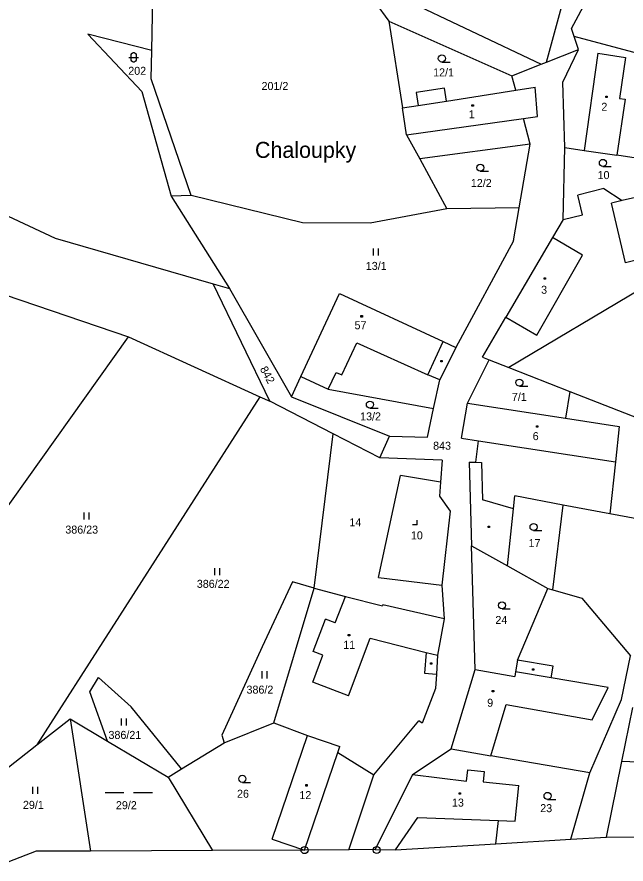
# Model space of a CAD drawing. Extents: x -791032 to -787751, y -1106872 to -1104403.
# Drawn here: x -789231 to -789101.8, y -1105221.6 to -1105041.7 of the extents above; entities that cross this region are included whole.
import ezdxf

# ---------------------------------------------------------------- set-up
doc = ezdxf.new("R2010")
doc.units = 0
for name, color, linetype in [('Vrstva 1', 7, 'Continuous'), ('Vrstva 14', 7, 'Continuous'), ('Vrstva 15', 7, 'Continuous'), ('Vrstva 2', 7, 'Continuous'), ('Vrstva 23', 7, 'Continuous'), ('Vrstva 25', 7, 'Continuous'), ('Vrstva 28', 7, 'Continuous'), ('Vrstva 36', 7, 'Continuous')]:
    doc.layers.add(name, color=color, linetype=linetype)

msp = doc.modelspace()

# ---------------------------------------------------------------- linework, layer by layer
at = {"layer": 'Vrstva 1'}
for p, q in [((-789178.54, -1105023.79), (-789119.8, -1105051.77)), ((-789113.36, -1105044.2), (-789102.89, -1105024.45)), ((-789202.43, -1105048.85), (-789202.19, -1105036.83)), ((-789155.02, -1105038.66), (-789152.12, -1105042.62)), ((-789118.67, -1105051.32), (-789115.06, -1105038.01)), ((-789152.12, -1105042.62), (-789126.03, -1105054.24)), ((-789152.12, -1105042.62), (-789149.25, -1105061.04)), ((-789112.82, -1105045.85), (-789113.36, -1105044.2)), ((-789202.43, -1105048.85), (-789215.98, -1105045.42)), ((-789215.98, -1105045.42), (-789204.53, -1105057.57)), ((-789098.24, -1105049.77), (-789112.82, -1105045.85)), ((-789111.91, -1105048.65), (-789112.82, -1105045.85)), ((-789202.55, -1105054.9), (-789202.43, -1105048.85)), ((-789118.67, -1105051.32), (-789111.91, -1105048.65)), ((-789115.2, -1105055.58), (-789111.91, -1105048.65)), ((-789119.8, -1105051.77), (-789118.67, -1105051.32)), ((-789126.03, -1105054.24), (-789119.8, -1105051.77)), ((-789194.11, -1105079.65), (-789202.55, -1105054.9)), ((-789125.2, -1105057.3), (-789126.03, -1105054.24)), ((-789140.29, -1105056.86), (-789146.31, -1105057.8)), ((-789139.86, -1105059.58), (-789140.29, -1105056.86)), ((-789125.2, -1105057.3), (-789121.04, -1105056.65)), ((-789120.61, -1105062.86), (-789121.04, -1105056.65)), ((-789114.79, -1105069.45), (-789115.2, -1105055.58)), ((-789204.53, -1105057.57), (-789198.35, -1105079.82)), ((-789146.31, -1105057.8), (-789145.89, -1105060.52)), ((-789139.86, -1105059.58), (-789125.2, -1105057.3)), ((-789149.25, -1105061.04), (-789145.89, -1105060.52)), ((-789148.36, -1105066.77), (-789149.25, -1105061.04)), ((-789278.51, -1105062.82), (-789222.93, -1105088.68)), ((-789123.58, -1105063.28), (-789120.61, -1105062.86)), ((-789122.11, -1105068.74), (-789123.58, -1105063.28)), ((-789148.36, -1105066.77), (-789145.58, -1105071.89)), ((-789122.11, -1105068.74), (-789145.58, -1105071.89)), ((-789124.47, -1105082.24), (-789122.11, -1105068.74)), ((-789115.1, -1105084.74), (-789114.79, -1105069.45)), ((-789114.79, -1105069.45), (-789110.65, -1105070.06)), ((-789110.65, -1105070.06), (-789103.77, -1105071.08)), ((-789098.72, -1105071.83), (-789103.77, -1105071.08)), ((-789145.58, -1105071.89), (-789139.84, -1105082.48)), ((-789106.48, -1105078.19), (-789112.04, -1105079.57)), ((-789106.48, -1105078.19), (-789102.58, -1105080.73)), ((-789194.11, -1105079.65), (-789198.35, -1105079.82)), ((-789198.35, -1105079.82), (-789185.94, -1105099.42)), ((-789170.48, -1105085.44), (-789194.11, -1105079.65)), ((-789111.01, -1105083.72), (-789112.04, -1105079.57)), ((-789098.52, -1105079.77), (-789102.58, -1105080.73)), ((-789139.84, -1105082.48), (-789156.07, -1105085.5)), ((-789124.47, -1105082.24), (-789139.84, -1105082.48)), ((-789125.7, -1105089.28), (-789124.47, -1105082.24)), ((-789115.1, -1105084.74), (-789111.01, -1105083.72)), ((-789156.07, -1105085.5), (-789170.48, -1105085.44)), ((-789115.1, -1105084.74), (-789117.37, -1105088.6)), ((-789222.93, -1105088.68), (-789189.39, -1105098.42)), ((-789117.37, -1105088.6), (-789127.27, -1105105.47)), ((-789125.7, -1105089.28), (-789137.94, -1105111.94)), ((-789177.4, -1105123.32), (-789189.39, -1105098.42)), ((-789189.39, -1105098.42), (-789185.94, -1105099.42)), ((-789185.94, -1105099.42), (-789172.78, -1105122.42)), ((-789098.56, -1105099.48), (-789126.63, -1105116.18)), ((-789233.54, -1105100.77), (-789207.36, -1105109.66)), ((-789170.78, -1105118.09), (-789162.62, -1105100.45)), ((-789162.62, -1105100.45), (-789140.61, -1105110.62)), ((-789132.26, -1105113.97), (-789127.27, -1105105.47)), ((-789249, -1105168.08), (-789207.36, -1105109.66)), ((-789207.36, -1105109.66), (-789179.49, -1105122.37)), ((-789140.61, -1105110.62), (-789137.94, -1105111.94)), ((-789137.94, -1105111.94), (-789141.33, -1105118.77)), ((-789132.26, -1105113.97), (-789130.85, -1105114.52)), ((-789135.42, -1105123.71), (-789130.85, -1105114.52)), ((-789130.85, -1105114.52), (-789126.63, -1105116.18)), ((-789126.63, -1105116.18), (-789113.73, -1105121.26)), ((-789172.78, -1105122.42), (-789170.78, -1105118.09)), ((-789170.78, -1105118.09), (-789164.97, -1105120.78)), ((-789142.62, -1105124.88), (-789141.33, -1105118.77)), ((-789164.97, -1105120.78), (-789142.62, -1105124.88)), ((-789113.73, -1105121.26), (-789114.64, -1105126.96)), ((-789113.73, -1105121.26), (-789084.71, -1105132.68)), ((-789179.49, -1105122.37), (-789226.84, -1105196.33)), ((-789179.49, -1105122.37), (-789177.4, -1105123.32)), ((-789163.93, -1105130.24), (-789177.4, -1105123.32)), ((-789172.78, -1105122.42), (-789152.02, -1105130.76)), ((-789143.9, -1105130.94), (-789142.62, -1105124.88)), ((-789136.72, -1105131.17), (-789135.42, -1105123.71)), ((-789135.42, -1105123.71), (-789114.64, -1105126.96)), ((-789114.64, -1105126.96), (-789103.28, -1105128.73)), ((-789103.28, -1105128.73), (-789104.06, -1105136.21)), ((-789167.98, -1105163.02), (-789163.93, -1105130.24)), ((-789154.05, -1105135.32), (-789163.93, -1105130.24)), ((-789154.05, -1105135.32), (-789152.02, -1105130.76)), ((-789152.02, -1105130.76), (-789143.9, -1105130.94)), ((-789136.72, -1105131.17), (-789133.11, -1105131.73)), ((-789133.7, -1105136.3), (-789133.11, -1105131.73)), ((-789140.82, -1105135.86), (-789154.05, -1105135.32)), ((-789140.82, -1105135.86), (-789141.17, -1105140.52)), ((-789135.08, -1105136.24), (-789133.7, -1105136.3)), ((-789135.08, -1105136.24), (-789134.56, -1105154.02)), ((-789104.06, -1105136.21), (-789105.22, -1105147.22)), ((-789154.31, -1105160.75), (-789149.66, -1105139.08)), ((-789141.17, -1105140.52), (-789149.66, -1105139.08)), ((-789141.17, -1105140.52), (-789141.4, -1105143.51)), ((-789141.4, -1105143.51), (-789139.12, -1105146.69)), ((-789125.68, -1105146.2), (-789125.39, -1105143.45)), ((-789115.14, -1105145.37), (-789125.39, -1105143.45)), ((-789139.12, -1105146.69), (-789140.86, -1105162.4)), ((-789126.93, -1105158.29), (-789125.68, -1105146.2)), ((-789117.31, -1105163.38), (-789115.14, -1105145.37)), ((-789105.22, -1105147.22), (-789115.14, -1105145.37)), ((-789086.15, -1105150.78), (-789105.22, -1105147.22)), ((-789134.56, -1105154.02), (-789126.93, -1105158.29)), ((-789133.79, -1105180.33), (-789134.56, -1105154.02)), ((-789126.93, -1105158.29), (-789118.36, -1105163.08)), ((-789154.31, -1105160.75), (-789140.86, -1105162.4)), ((-789172.59, -1105161.65), (-789179.02, -1105175.48)), ((-789176.5, -1105191.61), (-789167.98, -1105163.02)), ((-789167.98, -1105163.02), (-789172.59, -1105161.65)), ((-789167.98, -1105163.02), (-789161.34, -1105164.77)), ((-789140.86, -1105162.4), (-789140.4, -1105169.52)), ((-789161.34, -1105164.77), (-789153.5, -1105166.81)), ((-789124.81, -1105178.29), (-789118.36, -1105163.08)), ((-789118.36, -1105163.08), (-789117.31, -1105163.38)), ((-789117.31, -1105163.38), (-789111.16, -1105165.15)), ((-789153.41, -1105166.57), (-789153.5, -1105166.81)), ((-789140.4, -1105169.52), (-789153.41, -1105166.57)), ((-789111.16, -1105165.15), (-789100.83, -1105177.38)), ((-789140.4, -1105169.52), (-789141.8, -1105177.29)), ((-789179.02, -1105175.48), (-789187.58, -1105194.23)), ((-789141.8, -1105177.29), (-789142.03, -1105181.32)), ((-789102.76, -1105186.64), (-789100.83, -1105177.38)), ((-789124.81, -1105178.29), (-789125.24, -1105180.78)), ((-789138.91, -1105197.17), (-789133.79, -1105180.33)), ((-789133.79, -1105180.33), (-789125.41, -1105181.77)), ((-789125.24, -1105180.78), (-789125.41, -1105181.77)), ((-789215.56, -1105185.06), (-789213.74, -1105182.03)), ((-789213.74, -1105182.03), (-789206.78, -1105188.22)), ((-789142.03, -1105181.32), (-789142.21, -1105184.34)), ((-789142.21, -1105184.34), (-789145.07, -1105191.66)), ((-789211.8, -1105195.49), (-789215.56, -1105185.06)), ((-789109.47, -1105202.22), (-789102.76, -1105186.64)), ((-789196.13, -1105201.4), (-789206.78, -1105188.22)), ((-789102.69, -1105199.82), (-789100.37, -1105188.37)), ((-789226.84, -1105196.33), (-789219.72, -1105190.75)), ((-789219.72, -1105190.75), (-789215.47, -1105218.84)), ((-789219.72, -1105190.75), (-789211.8, -1105195.49)), ((-789187.04, -1105195.84), (-789176.5, -1105191.61)), ((-789176.5, -1105191.61), (-789169.41, -1105194.33)), ((-789155.31, -1105202.64), (-789145.74, -1105191.21)), ((-789145.07, -1105191.66), (-789145.74, -1105191.21)), ((-789187.58, -1105194.23), (-789187.04, -1105195.84)), ((-789176.91, -1105216.33), (-789169.41, -1105194.33)), ((-789169.41, -1105194.33), (-789162.53, -1105196.67)), ((-789235.62, -1105203.21), (-789226.84, -1105196.33)), ((-789211.8, -1105195.49), (-789198.99, -1105203.15)), ((-789196.13, -1105201.4), (-789187.04, -1105195.84)), ((-789162.95, -1105197.91), (-789162.53, -1105196.67)), ((-789147.12, -1105202.62), (-789138.91, -1105197.17)), ((-789138.91, -1105197.17), (-789130.48, -1105198.62)), ((-789162.95, -1105197.91), (-789155.31, -1105202.64)), ((-789109.47, -1105202.22), (-789130.48, -1105198.62)), ((-789105.94, -1105215.9), (-789102.69, -1105199.82)), ((-789096.99, -1105200.08), (-789102.69, -1105199.82)), ((-789198.99, -1105203.15), (-789196.13, -1105201.4)), ((-789135.62, -1105204), (-789135.39, -1105201.62)), ((-789135.39, -1105201.62), (-789131.9, -1105201.96)), ((-789131.9, -1105201.96), (-789132.12, -1105204.15)), ((-789113.53, -1105216.35), (-789109.47, -1105202.22)), ((-789198.99, -1105203.15), (-789189.58, -1105218.74)), ((-789160.6, -1105218.59), (-789155.31, -1105202.64)), ((-789147.12, -1105202.62), (-789155.06, -1105218.55)), ((-789147.12, -1105202.62), (-789135.62, -1105204)), ((-789132.12, -1105204.15), (-789124.56, -1105204.91)), ((-789125.32, -1105212.51), (-789124.56, -1105204.91)), ((-789129.42, -1105217.3), (-789128.85, -1105212.38)), ((-789128.85, -1105212.38), (-789125.32, -1105212.51)), ((-789176.91, -1105216.33), (-789170.03, -1105218.67)), ((-789129.42, -1105217.3), (-789113.53, -1105216.35)), ((-789113.53, -1105216.35), (-789105.94, -1105215.9)), ((-789105.94, -1105215.9), (-789070.94, -1105215.53)), ((-789189.58, -1105218.74), (-789215.47, -1105218.84)), ((-789170.03, -1105218.67), (-789189.58, -1105218.74)), ((-789160.6, -1105218.59), (-789170.03, -1105218.67)), ((-789155.06, -1105218.55), (-789160.6, -1105218.59)), ((-789155.06, -1105218.55), (-789150.68, -1105218.58)), ((-789150.68, -1105218.58), (-789129.42, -1105217.3)), ((-789226.96, -1105218.88), (-789243.84, -1105225.4)), ((-789215.47, -1105218.84), (-789226.96, -1105218.88))]:
    msp.add_line(p, q, dxfattribs=at)
at = {"layer": 'Vrstva 2'}
for p, q in [((-789107.8, -1105049.45), (-789110.65, -1105070.06)), ((-789107.8, -1105049.45), (-789101.91, -1105050.33)), ((-789101.91, -1105050.33), (-789103.2, -1105059.03)), ((-789145.89, -1105060.52), (-789139.86, -1105059.58)), ((-789102.01, -1105059.21), (-789103.77, -1105071.08)), ((-789103.2, -1105059.03), (-789102.01, -1105059.21)), ((-789148.36, -1105066.77), (-789123.58, -1105063.28)), ((-789102.58, -1105080.73), (-789104.9, -1105081.28)), ((-789101.92, -1105093.92), (-789104.9, -1105081.28)), ((-789111.01, -1105092.29), (-789117.37, -1105088.6)), ((-789120.75, -1105109.27), (-789111.01, -1105092.29)), ((-789095.52, -1105092.41), (-789101.92, -1105093.92)), ((-789127.27, -1105105.47), (-789120.75, -1105109.27)), ((-789143.82, -1105117.74), (-789140.61, -1105110.62)), ((-789162.13, -1105117.75), (-789158.95, -1105110.92)), ((-789158.95, -1105110.92), (-789143.82, -1105117.74)), ((-789164.97, -1105120.78), (-789163.31, -1105117.2)), ((-789163.31, -1105117.2), (-789162.13, -1105117.75)), ((-789141.33, -1105118.77), (-789143.82, -1105117.74)), ((-789133.11, -1105131.73), (-789104.06, -1105136.21)), ((-789133.7, -1105136.3), (-789132.48, -1105136.35)), ((-789132.48, -1105136.35), (-789132.25, -1105144.25)), ((-789125.68, -1105146.2), (-789132.25, -1105144.25)), ((-789163.49, -1105170.42), (-789161.34, -1105164.77)), ((-789168.19, -1105176.5), (-789165.58, -1105169.63)), ((-789163.49, -1105170.42), (-789165.58, -1105169.63)), ((-789160.71, -1105185.86), (-789156.09, -1105173.66)), ((-789156.09, -1105173.66), (-789144.22, -1105176.67)), ((-789168.28, -1105182.98), (-789166.11, -1105177.29)), ((-789166.11, -1105177.29), (-789168.19, -1105176.5)), ((-789144.22, -1105176.67), (-789144.57, -1105181.06)), ((-789144.22, -1105176.67), (-789141.8, -1105177.29)), ((-789117.26, -1105179.58), (-789124.81, -1105178.29)), ((-789117.69, -1105182.08), (-789125.24, -1105180.78)), ((-789117.69, -1105182.08), (-789117.26, -1105179.58)), ((-789144.57, -1105181.06), (-789142.03, -1105181.32)), ((-789105.6, -1105184.15), (-789117.69, -1105182.08)), ((-789160.71, -1105185.86), (-789168.28, -1105182.98)), ((-789109, -1105191), (-789105.6, -1105184.15)), ((-789130.48, -1105198.62), (-789127.21, -1105187.75)), ((-789127.21, -1105187.75), (-789109, -1105191)), ((-789170.03, -1105218.67), (-789162.95, -1105197.91)), ((-789150.68, -1105218.58), (-789146, -1105211.75)), ((-789146, -1105211.75), (-789128.85, -1105212.38))]:
    msp.add_line(p, q, dxfattribs=at)
at = {"layer": 'Vrstva 23'}
for p, q in [((-789206.78, -1105049.71), (-789206.68, -1105049.51)), ((-789206.68, -1105049.51), (-789206.58, -1105049.41)), ((-789206.58, -1105049.41), (-789206.38, -1105049.31)), ((-789206.38, -1105049.31), (-789206.18, -1105049.31)), ((-789206.18, -1105049.31), (-789205.98, -1105049.41)), ((-789205.98, -1105049.41), (-789205.88, -1105049.51)), ((-789205.88, -1105049.51), (-789205.78, -1105049.71)), ((-789207.28, -1105050.31), (-789205.28, -1105050.31)), ((-789206.78, -1105050.91), (-789206.78, -1105049.71)), ((-789206.68, -1105051.11), (-789206.78, -1105050.91)), ((-789206.58, -1105051.21), (-789206.68, -1105051.11)), ((-789206.38, -1105051.31), (-789206.58, -1105051.21)), ((-789206.18, -1105051.31), (-789206.38, -1105051.31)), ((-789205.98, -1105051.21), (-789206.18, -1105051.31)), ((-789205.88, -1105051.11), (-789205.98, -1105051.21)), ((-789205.78, -1105050.91), (-789205.88, -1105051.11)), ((-789205.78, -1105049.71), (-789205.78, -1105050.91)), ((-789140.88, -1105051.3), (-789139.13, -1105051.3)), ((-789132.72, -1105074.49), (-789130.97, -1105074.49)), ((-789106.7, -1105073.47), (-789104.95, -1105073.47)), ((-789155.39, -1105092.41), (-789155.39, -1105090.91)), ((-789154.39, -1105090.91), (-789154.39, -1105092.41)), ((-789124.41, -1105120.13), (-789122.66, -1105120.13)), ((-789156.15, -1105124.8), (-789154.4, -1105124.8)), ((-789216.79, -1105148.46), (-789216.79, -1105146.96)), ((-789215.79, -1105146.96), (-789215.79, -1105148.46)), ((-789146.13, -1105149.58), (-789146.13, -1105148.58)), ((-789146.13, -1105149.58), (-789147.13, -1105149.58)), ((-789121.41, -1105150.79), (-789119.66, -1105150.79)), ((-789189.05, -1105160.26), (-789189.05, -1105158.76)), ((-789188.05, -1105158.76), (-789188.05, -1105160.26)), ((-789128.11, -1105167.43), (-789126.36, -1105167.43)), ((-789179.01, -1105182.18), (-789179.01, -1105180.68)), ((-789178.01, -1105180.68), (-789178.01, -1105182.18)), ((-789208.86, -1105192.22), (-789208.86, -1105190.72)), ((-789207.86, -1105190.72), (-789207.86, -1105192.22)), ((-789183.21, -1105204.26), (-789181.46, -1105204.26)), ((-789227.67, -1105206.69), (-789227.67, -1105205.19)), ((-789226.67, -1105205.19), (-789226.67, -1105206.69)), ((-789212.355, -1105206.42), (-789208.335, -1105206.42)), ((-789206.325, -1105206.42), (-789202.305, -1105206.42)), ((-789118.44, -1105207.89), (-789116.69, -1105207.89))]:
    msp.add_line(p, q, dxfattribs=at)
for centre in [(-789140.88, -1105050.55), (-789132.72, -1105073.74), (-789106.7, -1105072.72), (-789124.41, -1105119.38), (-789156.15, -1105124.05), (-789121.41, -1105150.04), (-789128.11, -1105166.68), (-789183.21, -1105203.51), (-789118.44, -1105207.14)]:
    msp.add_circle(centre, 0.75, dxfattribs=at)
at = {"layer": 'Vrstva 25'}
for p, q in [((-789106.11, -1105058.57), (-789105.81, -1105058.57)), ((-789106.11, -1105058.87), (-789106.11, -1105058.57)), ((-789105.81, -1105058.57), (-789105.81, -1105058.87)), ((-789134.48, -1105060.36), (-789134.18, -1105060.36)), ((-789134.48, -1105060.66), (-789134.48, -1105060.36)), ((-789134.18, -1105060.36), (-789134.18, -1105060.66)), ((-789105.81, -1105058.87), (-789106.11, -1105058.87)), ((-789134.18, -1105060.66), (-789134.48, -1105060.66)), ((-789119.16, -1105097.13), (-789118.86, -1105097.13)), ((-789119.16, -1105097.43), (-789119.16, -1105097.13)), ((-789118.86, -1105097.43), (-789119.16, -1105097.43)), ((-789118.86, -1105097.13), (-789118.86, -1105097.43)), ((-789158.05, -1105105.15), (-789157.75, -1105105.15)), ((-789158.05, -1105105.45), (-789158.05, -1105105.15)), ((-789157.75, -1105105.45), (-789158.05, -1105105.45)), ((-789157.75, -1105105.15), (-789157.75, -1105105.45)), ((-789141.1, -1105114.66), (-789140.8, -1105114.66)), ((-789141.1, -1105114.96), (-789141.1, -1105114.66)), ((-789140.8, -1105114.96), (-789141.1, -1105114.96)), ((-789140.8, -1105114.66), (-789140.8, -1105114.96)), ((-789120.82, -1105128.53), (-789120.52, -1105128.53)), ((-789120.82, -1105128.83), (-789120.82, -1105128.53)), ((-789120.52, -1105128.83), (-789120.82, -1105128.83)), ((-789120.52, -1105128.53), (-789120.52, -1105128.83)), ((-789131.04, -1105149.88), (-789130.74, -1105149.88)), ((-789131.04, -1105150.18), (-789131.04, -1105149.88)), ((-789130.74, -1105150.18), (-789131.04, -1105150.18)), ((-789130.74, -1105149.88), (-789130.74, -1105150.18)), ((-789160.73, -1105172.88), (-789160.43, -1105172.88)), ((-789160.73, -1105173.18), (-789160.73, -1105172.88)), ((-789160.43, -1105173.18), (-789160.73, -1105173.18)), ((-789160.43, -1105172.88), (-789160.43, -1105173.18)), ((-789143.31, -1105178.9), (-789143.01, -1105178.9)), ((-789143.31, -1105179.2), (-789143.31, -1105178.9)), ((-789143.01, -1105179.2), (-789143.31, -1105179.2)), ((-789143.01, -1105178.9), (-789143.01, -1105179.2)), ((-789121.64, -1105180.17), (-789121.34, -1105180.17)), ((-789121.64, -1105180.47), (-789121.64, -1105180.17)), ((-789121.34, -1105180.47), (-789121.64, -1105180.47)), ((-789121.34, -1105180.17), (-789121.34, -1105180.47)), ((-789130.17, -1105184.74), (-789129.87, -1105184.74)), ((-789130.17, -1105185.04), (-789130.17, -1105184.74)), ((-789129.87, -1105185.04), (-789130.17, -1105185.04)), ((-789129.87, -1105184.74), (-789129.87, -1105185.04)), ((-789169.75, -1105204.75), (-789169.45, -1105204.75)), ((-789169.75, -1105205.05), (-789169.75, -1105204.75)), ((-789169.45, -1105205.05), (-789169.75, -1105205.05)), ((-789169.45, -1105204.75), (-789169.45, -1105205.05)), ((-789137.21, -1105206.49), (-789136.91, -1105206.49)), ((-789137.21, -1105206.79), (-789137.21, -1105206.49)), ((-789136.91, -1105206.79), (-789137.21, -1105206.79)), ((-789136.91, -1105206.49), (-789136.91, -1105206.79))]:
    msp.add_line(p, q, dxfattribs=at)
at = {"layer": 'Vrstva 28'}
for centre, radius in [((-789170.01, -1105218.65), 0.75), ((-789170.01, -1105218.65), 0.01), ((-789154.7, -1105218.62), 0.75), ((-789154.7, -1105218.62), 0.01)]:
    msp.add_circle(centre, radius, dxfattribs=at)

# ---------------------------------------------------------------- texts
at = {"layer": 'Vrstva 14'}
for s, p in [('202', (-789207.426, -1105054.02)), ('12/1', (-789142.726, -1105054.35)), ('201/2', (-789179.142, -1105057.25)), ('10', (-789107.829, -1105076.16)), ('12/2', (-789134.723, -1105077.84)), ('13/1', (-789157.017, -1105095.45)), ('7/1', (-789126.02, -1105123.25)), ('13/2', (-789158.223, -1105127.4)), ('843', (-789142.732, -1105133.63)), ('14', (-789160.506, -1105149.89)), ('386/23', (-789220.78, -1105151.44)), ('17', (-789122.487, -1105154.31)), ('386/22', (-789192.879, -1105162.96)), ('24', (-789129.522, -1105170.63)), ('386/2', (-789182.33, -1105185.42)), ('386/21', (-789211.623, -1105195.04)), ('26', (-789184.347, -1105207.53)), ('29/1', (-789229.773, -1105209.89)), ('29/2', (-789210.04, -1105209.96)), ('23', (-789119.997, -1105210.59))]:
    msp.add_text(s, height=1.7, dxfattribs=at).set_placement(p)
msp.add_text('842', height=1.7, rotation=298.69488, dxfattribs=at).set_placement((-789179.543, -1105116.474))
at = {"layer": 'Vrstva 15'}
for s, p in [('2', (-789107.027, -1105061.66)), ('1', (-789135.17, -1105063.24)), ('3', (-789119.817, -1105100.51)), ('57', (-789159.41, -1105108.05)), ('6', (-789121.597, -1105131.59)), ('10', (-789147.449, -1105152.67)), ('11', (-789161.813, -1105175.91)), ('9', (-789131.257, -1105188.21)), ('12', (-789171.11, -1105207.82)), ('13', (-789138.73, -1105209.41))]:
    msp.add_text(s, height=1.7, dxfattribs=at).set_placement(p)
at = {"layer": 'Vrstva 36'}
msp.add_text('Chaloupky', height=3.4, dxfattribs=at).set_placement((-789180.53, -1105071.66))

doc.saveas('drawing.dxf')
